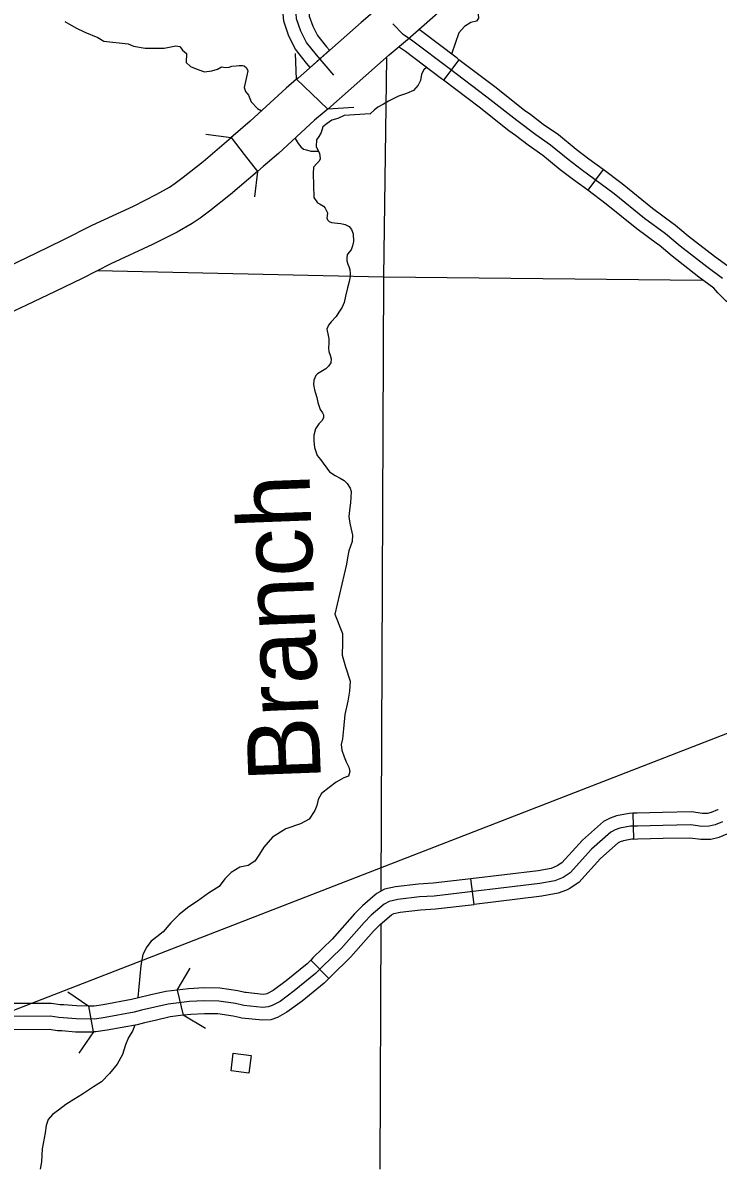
# Model space of a CAD drawing. Extents: x 61396 to 64680, y 55472 to 57605.
# Drawn here: x 62051.4 to 62177.9, y 55723.8 to 55932.3 of the extents above; entities that cross this region are included whole.
import ezdxf

# ---------------------------------------------------------------- set-up
doc = ezdxf.new("R2010")
doc.units = 0
for name, color, linetype in [('15', 7, 'Continuous'), ('31', 7, 'Continuous'), ('35', 7, 'Continuous'), ('37', 7, 'Continuous'), ('38', 7, 'Continuous'), ('45', 7, 'Continuous'), ('5', 7, 'Continuous'), ('56', 7, 'Continuous'), ('57', 7, 'Continuous'), ('Default', 7, 'Continuous')]:
    doc.layers.add(name, color=color, linetype=linetype)

msp = doc.modelspace()

# ---------------------------------------------------------------- linework, layer by layer
at = {"layer": '15'}
for points in [[(62125.51, 55943.32), (62116.27, 55935.2), (62112.92, 55932.37), (62101.46, 55922.26), (62101.2, 55922.04)], [(62101.2, 55922.04), (62103.89, 55919.47), (62106.87, 55916.62), (62118.03, 55926.46), (62121.37, 55929.29), (62131.04, 55937.79), (62128.16, 55940.67), (62125.51, 55943.32)], [(62048.7, 55887.99), (62053.87, 55890.44), (62058.69, 55892.8), (62063.98, 55895.48), (62071.54, 55898.97), (62075.77, 55901.13), (62078.04, 55902.39), (62079.09, 55903.13), (62080.57, 55904.21), (62084.17, 55907.1), (62089.28, 55911.44), (62091.68, 55908.37), (62094.09, 55905.28)], [(62094.09, 55905.28), (62089.14, 55901.07), (62085.32, 55898.01), (62083.65, 55896.78), (62082.19, 55895.76), (62079.44, 55894.23), (62074.95, 55891.94), (62067.39, 55888.44), (62062.17, 55885.8), (62057.26, 55883.4), (62052.03, 55880.92), (62048.98, 55879.49)]]:
    msp.add_lwpolyline(points, dxfattribs=at)
at = {"layer": '31'}
for p, q in [((62162.38, 55788.48), (62162.49, 55783.79)), ((62133.48, 55771.92), (62132.92, 55776.58)), ((62103.79, 55761.78), (62107.05, 55758.42)), ((62079.46, 55756.32), (62080.58, 55751.73)), ((62064.23, 55748.71), (62063.37, 55753.41))]:
    msp.add_line(p, q, dxfattribs=at)
for points in [[(62107.96, 55922.78), (62104.8, 55926.46), (62102.99, 55928.75), (62101.96, 55930.78), (62101.17, 55933.05), (62101.12, 55933.97), (62101.17, 55935.76), (62101.85, 55939.58), (62102.79, 55945.61), (62103.08, 55947.39)], [(62177.89, 55789.13), (62177.8, 55789.1), (62176.64, 55788.64), (62175.94, 55788.46), (62175.06, 55788.44), (62173.08, 55788.75), (62167.77, 55788.62), (62163.15, 55788.5), (62162.38, 55788.48)], [(62178.67, 55786.92), (62177.36, 55786.4), (62176.26, 55786.13), (62174.91, 55786.09), (62172.93, 55786.4), (62167.83, 55786.28), (62163.21, 55786.16), (62161.96, 55786.13), (62160.04, 55785.76), (62159.18, 55785.45), (62158.39, 55785.06), (62154.85, 55781.94), (62151, 55777.67), (62149.71, 55776.81), (62148.16, 55776.2), (62145.48, 55775.72), (62126.24, 55773.42), (62123.57, 55773.28), (62119.61, 55772.81), (62118.04, 55772.46), (62117.11, 55771.94), (62114.77, 55769.96), (62113.46, 55768.61), (62109.36, 55763.97), (62105.81, 55760.48), (62104.66, 55759.36), (62100.75, 55756.16), (62098.19, 55754.27), (62096.75, 55753.5), (62096.04, 55753.25), (62095.05, 55753.18), (62091.58, 55753.54), (62090.07, 55753.9), (62087.03, 55754.32), (62084.38, 55754.36), (62081.73, 55754.25), (62077.8, 55753.74), (62072.97, 55752.65), (62071.65, 55752.3), (62066.35, 55751.33), (62064.48, 55751.05), (62061.06, 55751.09), (62057.94, 55751.33), (62056.34, 55751.56), (62049.53, 55751.52)], [(62162.38, 55788.48), (62161.71, 55788.46), (62159.42, 55788.03), (62158.26, 55787.61), (62157.07, 55787.02), (62153.2, 55783.61), (62149.45, 55779.45), (62148.62, 55778.9), (62148.62, 55778.9)], [(62162.49, 55783.79), (62163.27, 55783.81), (62167.89, 55783.94), (62172.78, 55784.05), (62174.76, 55783.75), (62176.57, 55783.79), (62178.07, 55784.16), (62179.54, 55784.74), (62179.64, 55784.79)], [(62162.49, 55783.79), (62162.21, 55783.79), (62160.65, 55783.49), (62160.1, 55783.29), (62159.71, 55783.1), (62156.5, 55780.27), (62152.54, 55775.88), (62150.8, 55774.72), (62150.33, 55774.53)], [(62148.62, 55778.9), (62147.52, 55778.47), (62145.13, 55778.04), (62132.92, 55776.58)], [(62132.92, 55776.58), (62126.04, 55775.75), (62123.37, 55775.61), (62119.21, 55775.12), (62117.2, 55774.67), (62115.77, 55773.88), (62115.47, 55773.63)], [(62150.33, 55774.53), (62148.8, 55773.93), (62145.83, 55773.4), (62133.48, 55771.92)], [(62115.47, 55773.63), (62113.17, 55771.67), (62111.74, 55770.21), (62107.66, 55765.59), (62104.17, 55762.16), (62103.79, 55761.78)], [(62118.45, 55770), (62118.88, 55770.24), (62120.01, 55770.49), (62123.76, 55770.94), (62126.44, 55771.08), (62133.48, 55771.92)], [(62107.05, 55758.42), (62107.45, 55758.81), (62111.07, 55762.36), (62115.18, 55767.02), (62116.38, 55768.24), (62118.45, 55770)], [(62103.79, 55761.78), (62103.09, 55761.11), (62099.31, 55758.01), (62096.94, 55756.26), (62095.79, 55755.65), (62095.56, 55755.56), (62095.1, 55755.53), (62091.97, 55755.86), (62091.78, 55755.9)], [(62107.05, 55758.42), (62106.22, 55757.61), (62102.19, 55754.31), (62099.44, 55752.28), (62097.71, 55751.36), (62096.53, 55750.93), (62095, 55750.83), (62091.2, 55751.23), (62090.73, 55751.34)], [(62074.41, 55755.38), (62072.41, 55754.93), (62071.14, 55754.59), (62065.97, 55753.64), (62064.33, 55753.4), (62063.37, 55753.41)], [(62079.46, 55756.32), (62077.39, 55756.05), (62074.41, 55755.38)], [(62091.78, 55755.9), (62090.49, 55756.2), (62087.21, 55756.66), (62084.35, 55756.71), (62081.53, 55756.58), (62079.46, 55756.32)], [(62058.81, 55753.61), (62058.2, 55753.66), (62056.51, 55753.9), (62049.48, 55753.86), (62046.36, 55753.75), (62042.21, 55753.84)], [(62063.37, 55753.41), (62061.16, 55753.43), (62058.81, 55753.61)], [(62080.58, 55751.73), (62078.21, 55751.43), (62075.44, 55750.8)], [(62090.73, 55751.34), (62089.64, 55751.59), (62086.85, 55751.98), (62084.42, 55752.02), (62081.93, 55751.91), (62080.58, 55751.73)], [(62042.1, 55749.15), (62046.39, 55749.06), (62049.58, 55749.18), (62056.18, 55749.21), (62057.68, 55748.99), (62058.46, 55748.94)], [(62058.46, 55748.94), (62060.96, 55748.75), (62064.23, 55748.71)], [(62075.44, 55750.8), (62073.53, 55750.37), (62072.16, 55750.01), (62066.73, 55749.01), (62064.64, 55748.71), (62064.23, 55748.71)]]:
    msp.add_lwpolyline(points, dxfattribs=at)
at = {"layer": '35'}
for points in [[(62132.65, 55938.88), (62133.29, 55936.59), (62133.9, 55935.26), (62134.18, 55934.43), (62134.28, 55933.17), (62133.96, 55932.59), (62132.92, 55932.38), (62131.72, 55931.65), (62130.73, 55930.46), (62129.38, 55926.61)], [(62059.03, 55932.52), (62061, 55931.4), (62062.65, 55930.63), (62065, 55929.62), (62066.14, 55928.99), (62070.56, 55928.5), (62071.52, 55928.05), (62073.64, 55927.71), (62077.08, 55927.71), (62079.24, 55928.09), (62079.92, 55927.98), (62080.45, 55927.34), (62081.13, 55926.69), (62081.1, 55925.06), (62081.88, 55924.37), (62082.89, 55923.93), (62084.46, 55923.36), (62085.75, 55923.59), (62086.77, 55923.85), (62087.5, 55924.27), (62088.26, 55924.2), (62088.91, 55924.25), (62089.41, 55924.39), (62090.19, 55924.48), (62090.75, 55924.56), (62091.35, 55924.52), (62091.66, 55924.47), (62092.05, 55924.13), (62092.32, 55923.58), (62092.13, 55922.72), (62091.63, 55920.54), (62091.9, 55919.8), (62092.45, 55919.16), (62092.94, 55917.91), (62094.08, 55916.7), (62094.78, 55916.26)], [(62124.84, 55924.15), (62124.36, 55923.75), (62123.91, 55922.95), (62123.73, 55921.82), (62123.32, 55920.96), (62122.47, 55919.99), (62121.2, 55919.42), (62119.75, 55918.93), (62117.93, 55918.06), (62117, 55917.52), (62115.96, 55916.93), (62115.28, 55916.43), (62114.58, 55915.75), (62114.51, 55915.62)], [(62114.58, 55915.75), (62109.87, 55915.41), (62108.7, 55914.87), (62107.61, 55914.56), (62106.76, 55914.01), (62105.94, 55913.38), (62105.69, 55912.34), (62105.24, 55911.64), (62104.79, 55911.03), (62104.74, 55909.8), (62105.07, 55909.15), (62105.37, 55908.56), (62105.49, 55907.53), (62105.32, 55907.12), (62104.86, 55906.7), (62104.29, 55906.02), (62104.2, 55904.86), (62104.33, 55900.53), (62105.02, 55899.58), (62105.46, 55899.31), (62106.07, 55898.95), (62106.4, 55898.55), (62106.8, 55897.75), (62106.75, 55897.19), (62106.7, 55896.84), (62106.8, 55896.47), (62107.13, 55896.13), (62107.54, 55895.96), (62108.61, 55895.86), (62109.27, 55895.79), (62110.03, 55895.6), (62110.76, 55895.27), (62111.18, 55894.72), (62111.49, 55893.88), (62111.56, 55892.54), (62111.36, 55891.75), (62111.11, 55890.98), (62110.71, 55890.5), (62110.38, 55890.11), (62110.31, 55889.52), (62110.35, 55889.01), (62110.53, 55888.42), (62110.67, 55887.99), (62110.87, 55887.4), (62110.96, 55886.71), (62110.97, 55886.15), (62110.75, 55885.26), (62110.44, 55884.06), (62110.11, 55882.57), (62109.86, 55881.44), (62109.48, 55880.55), (62108.88, 55879.65), (62108.38, 55878.88), (62107.5, 55877.91), (62107.01, 55877.3), (62106.72, 55876.57), (62106.92, 55875.44), (62107.06, 55874.79), (62107.08, 55874.1), (62106.99, 55873.09), (62107.07, 55872.53), (62107.31, 55871.81), (62107.51, 55871.19), (62107.44, 55870.47), (62106.99, 55869.83), (62106.51, 55869.37), (62105.61, 55868.81), (62105, 55868.44), (62104.7, 55868.12), (62104.35, 55867.29), (62104.28, 55866.51), (62104.43, 55865.51), (62104.64, 55864.95), (62104.88, 55864.11), (62105.07, 55863.21), (62105.31, 55862.52), (62105.51, 55861.93), (62105.91, 55861.32)], [(62100.92, 55911.27), (62101.5, 55910.37), (62101.96, 55909.73), (62102.47, 55909.3), (62102.97, 55909.2), (62103.76, 55908.97), (62104.27, 55908.95), (62105.18, 55908.93)], [(62105.91, 55861.32), (62106.11, 55860.95), (62106.06, 55860.41), (62105.76, 55859.9), (62105.22, 55859.32), (62104.65, 55858.45), (62104.31, 55857.31), (62104.31, 55856.21), (62104.47, 55855.03), (62104.92, 55853.57), (62105.57, 55852.87), (62107.2, 55850.63), (62108.2, 55849.97), (62109.15, 55849.43), (62109.85, 55849.05), (62110.4, 55848.5), (62110.93, 55847.64), (62111.1, 55847.02), (62111.08, 55845.92), (62110.98, 55844.94), (62110.91, 55844.12), (62110.71, 55842.48), (62110.8, 55841.61), (62110.94, 55840.99), (62111.35, 55839.08), (62111.32, 55837.92), (62111, 55837.1), (62110.68, 55836.21), (62110.44, 55834.98), (62110.29, 55833.84), (62108.17, 55824.7)], [(62108.17, 55824.7), (62109.56, 55821.17), (62109.57, 55819.5), (62109.5, 55817.27), (62110.09, 55815.11), (62110.96, 55812.52), (62110.79, 55810.73), (62110.49, 55808.87), (62109.98, 55806.45), (62109.73, 55803.84), (62109.52, 55802.02), (62109.28, 55800.98), (62109.45, 55799.98), (62109.84, 55798.76), (62110.22, 55797.85), (62110.67, 55796.85), (62110.9, 55796.07), (62110.63, 55795.22), (62109.81, 55794.93), (62108.38, 55794.16), (62107.14, 55793.2), (62105.74, 55792.09), (62105.12, 55791.02), (62104.85, 55789.88), (62104.54, 55788.97), (62103.49, 55787.39), (62101.93, 55786.56), (62099.22, 55785.68), (62096.79, 55784.15), (62095.21, 55782.34), (62094.47, 55781.05), (62093.6, 55779.78), (62092.35, 55778.99), (62090.88, 55778.69), (62089.29, 55777.73), (62088.11, 55776.59), (62087.09, 55775.16), (62085.19, 55773.95), (62083.14, 55772.52), (62081.58, 55771.47), (62079.81, 55770.1), (62078.32, 55768.58), (62076.89, 55766.93), (62075.74, 55766.01), (62074.72, 55765.21), (62073.97, 55764.17), (62073.24, 55762.78), (62072.82, 55760.8), (62072.31, 55754.95), (62072.3, 55754.87)], [(62071.78, 55749.93), (62071.34, 55748.85), (62070.59, 55747.68), (62070.04, 55746.39), (62069.5, 55744.59), (62068.57, 55742.86), (62067.15, 55741.15), (62065.69, 55739.63), (62064.26, 55738.73), (62062.23, 55737.36), (62060.64, 55736.44), (62059.21, 55735.51), (62057.84, 55734.46), (62056.78, 55733.66), (62056.01, 55732.78), (62055.64, 55731.71), (62055.47, 55730.35), (62054.9, 55727.46), (62054.77, 55725.1), (62054.52, 55723.76)]]:
    msp.add_lwpolyline(points, dxfattribs=at)
at = {"layer": '37'}
for points in [[(62101.2, 55922.04), (62101.01, 55926.72)], [(62111.62, 55916.92), (62106.87, 55916.62)], [(62084.65, 55912.04), (62089.28, 55911.44)], [(62094.09, 55905.28), (62093.51, 55900.63)]]:
    msp.add_lwpolyline(points, dxfattribs=at)
at = {"layer": '38'}
for points in [[(62079.46, 55756.32), (62081.84, 55760.3)], [(62059.54, 55755.99), (62063.37, 55753.41)], [(62084.6, 55749.33), (62080.58, 55751.73)], [(62064.23, 55748.71), (62061.56, 55744.86)]]:
    msp.add_lwpolyline(points, dxfattribs=at)
at = {"layer": '45'}
for p, q in [((62130.74, 55925.59), (62127.91, 55921.85)), ((62156.97, 55905.59), (62154.16, 55901.84))]:
    msp.add_line(p, q, dxfattribs=at)
for points in [[(62178.72, 55885.78), (62175.83, 55887.92), (62170.99, 55891.68), (62168.3, 55893.9), (62164.53, 55896.68), (62158.98, 55901.16), (62153, 55905.63), (62150.62, 55907.42), (62147.41, 55910.03), (62144.72, 55911.93), (62141.27, 55914.51), (62135.84, 55918.79), (62128.98, 55923.98), (62122.36, 55928.98), (62120.58, 55930.2), (62118.69, 55932.14)], [(62130.74, 55925.59), (62130.39, 55925.85), (62123.73, 55930.88), (62123.42, 55931.09)], [(62127.91, 55921.85), (62127.57, 55922.11), (62120.99, 55927.07), (62119.76, 55927.92)], [(62143.81, 55915.54), (62142.69, 55916.37), (62137.27, 55920.65), (62130.74, 55925.59)], [(62141, 55911.78), (62139.84, 55912.65), (62134.4, 55916.94), (62127.91, 55921.85)], [(62156.97, 55905.59), (62154.4, 55907.51), (62152.06, 55909.26), (62148.83, 55911.9), (62146.09, 55913.83), (62143.81, 55915.54)], [(62154.16, 55901.84), (62151.59, 55903.76), (62149.18, 55905.57), (62145.99, 55908.16), (62143.34, 55910.04), (62141, 55911.78)], [(62170.12, 55895.44), (62169.74, 55895.75), (62165.96, 55898.53), (62160.42, 55903.01), (62156.97, 55905.59)], [(62167.14, 55891.82), (62166.86, 55892.05), (62163.1, 55894.82), (62157.54, 55899.3), (62154.16, 55901.84)], [(62182.74, 55884.97), (62182.51, 55885.15), (62181.31, 55886.38), (62180.32, 55887.52), (62177.24, 55889.79), (62172.46, 55893.51), (62170.12, 55895.44)], [(62179.86, 55881.27), (62179.37, 55881.65), (62177.87, 55883.2), (62177.13, 55884.04), (62174.41, 55886.05), (62169.53, 55889.85), (62167.14, 55891.82)]]:
    msp.add_lwpolyline(points, dxfattribs=at)
at = {"layer": '5'}
for points in [[(62117.54, 55925.95), (62117.02, 55886.1)], [(62064.99, 55887.22), (62117.02, 55886.1)], [(62117.02, 55886.1), (62116.55, 55774.31)], [(62117.02, 55886.1), (62175.01, 55885.49)], [(62116.52, 55768.36), (62116.33, 55723.76)]]:
    msp.add_lwpolyline(points, dxfattribs=at)
at = {"layer": '56'}
for points in [[(62101.2, 55922.04), (62099.29, 55920.42), (62092.75, 55914.39), (62090.07, 55912.12), (62089.28, 55911.44)], [(62106.87, 55916.62), (62106.57, 55916.35), (62104.47, 55914.56), (62097.92, 55908.53), (62095.13, 55906.16), (62094.09, 55905.28)]]:
    msp.add_lwpolyline(points, dxfattribs=at)
msp.add_lwpolyline([(62089.28, 55741.61), (62089.67, 55744.84), (62092.91, 55744.45), (62092.52, 55741.22)], close=True, dxfattribs=at)
at = {"layer": '57'}
msp.add_line((62107.17, 55927.3), (62103.66, 55924.2), dxfattribs=at)
for points in [[(62103.66, 55924.2), (62103, 55924.97), (62101, 55927.48), (62099.8, 55929.86), (62098.85, 55932.59), (62098.77, 55933.94), (62098.83, 55936), (62099.1, 55937.49)], [(62103.71, 55936.66), (62103.51, 55935.52), (62103.46, 55934), (62103.49, 55933.51), (62104.12, 55931.7), (62104.97, 55930.02), (62106.61, 55927.95), (62107.17, 55927.3)]]:
    msp.add_lwpolyline(points, dxfattribs=at)
at = {"layer": 'Default'}
msp.add_line((62046.64, 55751.5), (62762.7, 56029.16), dxfattribs=at)

# ---------------------------------------------------------------- texts
at = {"layer": '35'}
msp.add_text('Branch', height=13.2, rotation=92.1813, dxfattribs=at).set_placement((62105.64, 55794.48))

doc.saveas('drawing.dxf')
